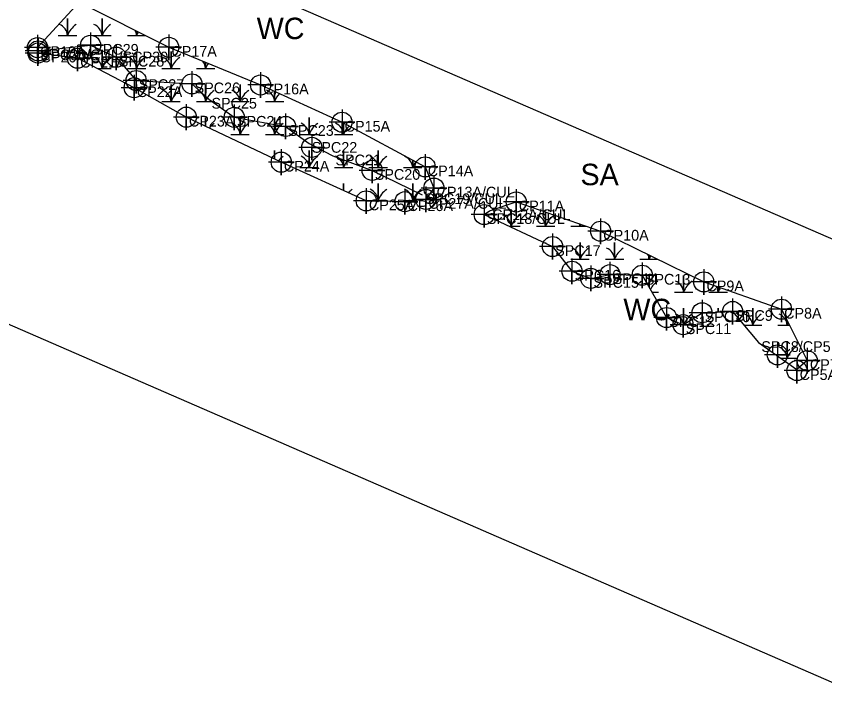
# Model space of a CAD drawing. Extents: x 1253697 to 1278588, y 912189 to 981699.
# Drawn here: x 1258689 to 1259443, y 914396 to 915036 of the extents above; entities that cross this region are included whole.
import ezdxf

# ---------------------------------------------------------------- set-up
doc = ezdxf.new("R2010")
doc.units = 0
for name, color, linetype in [('Default', 7, 'Continuous'), ('Exist Environmental Wetland Boundary', 7, 'Continuous'), ('Exist Environmental Wetland Boundary Cogo Comment', 7, 'Continuous'), ('Exist Environmental Wetland Boundary Cogo Number', 7, 'Continuous'), ('Exist Environmental Wetland Boundary Cogo Point CELL', 7, 'Continuous'), ('Exist Hydro Jurisdictional Stream or Body of Water Mitigable', 7, 'Continuous'), ('Exist Hydro Jurisdictional Stream or Body of Water Mitigable Cogo Comment', 7, 'Continuous'), ('Exist Hydro Jurisdictional Stream or Body of Water Mitigable Cogo Number', 7, 'Continuous'), ('Exist Hydro Jurisdictional Stream or Body of Water Mitigable Cogo Point CELL', 7, 'Continuous'), ('Exist Hydro Swamp or Marsh', 7, 'Continuous')]:
    doc.layers.add(name, color=color, linetype=linetype)

msp = doc.modelspace()

# ---------------------------------------------------------------- linework, layer by layer
at = {"layer": 'Default'}
for points in [[(1259882.27, 914640.07), (1258730.68, 915140.33), (1258752.58, 915140.13), (1259232.78, 915134.84)], [(1259882.27, 914640.07), (1258730.68, 915140.33), (1258752.58, 915140.13), (1259232.78, 915134.84)], [(1259882.27, 914640.07), (1258730.68, 915140.33), (1258752.58, 915140.13), (1259232.78, 915134.84)], [(1259882.27, 914640.07), (1258730.68, 915140.33), (1258752.58, 915140.13), (1259232.78, 915134.84)], [(1258166.63, 914972.26), (1258388.79, 914875.66), (1259491.8, 914396.09)], [(1258166.63, 914972.26), (1258388.79, 914875.66), (1259491.8, 914396.09)], [(1258166.63, 914972.26), (1258388.79, 914875.66), (1259491.8, 914396.09)], [(1258166.63, 914972.26), (1258388.79, 914875.66), (1259491.8, 914396.09)]]:
    msp.add_lwpolyline(points, dxfattribs=at)
at = {"layer": 'Exist Environmental Wetland Boundary'}
msp.add_lwpolyline([(1258708.45, 915006.43), (1258747.36, 915048.9), (1258830.9, 915006.73), (1258916.61, 914971.6), (1258992.57, 914936.81), (1259070.12, 914895.18), (1259078.33, 914875.39), (1259070.72, 914864.84), (1259051.29, 914862.72), (1259015.2, 914863.46), (1258935.87, 914899.57), (1258847.29, 914941.57), (1258798.67, 914969.06), (1258745.83, 914996.58), (1258708.91, 915001.42)], close=True, dxfattribs=at)
msp.add_lwpolyline([(1259125.23, 914850.69), (1259130.26, 914854.3), (1259155.09, 914862.43), (1259233.84, 914835.13), (1259330.1, 914787.85), (1259402.59, 914762.39), (1259426.59, 914714.42), (1259416.94, 914706.11)], dxfattribs=at)
at = {"layer": 'Exist Environmental Wetland Boundary Cogo Point CELL'}
for points in [[(1258708.45, 915018.43), (1258708.45, 914994.43), (1258708.45, 915006.43), (1258720.45, 915006.43), (1258696.45, 915006.43)], [(1258830.9, 915018.73), (1258830.9, 914994.73), (1258830.9, 915006.73), (1258842.9, 915006.73), (1258818.9, 915006.73)], [(1258708.91, 915013.42), (1258708.91, 914989.42), (1258708.91, 915001.42), (1258720.91, 915001.42), (1258696.91, 915001.42)], [(1258745.83, 915008.58), (1258745.83, 914984.58), (1258745.83, 914996.58), (1258757.83, 914996.58), (1258733.83, 914996.58)], [(1258798.67, 914981.06), (1258798.67, 914957.06), (1258798.67, 914969.06), (1258810.67, 914969.06), (1258786.67, 914969.06)], [(1258916.61, 914983.6), (1258916.61, 914959.6), (1258916.61, 914971.6), (1258928.61, 914971.6), (1258904.61, 914971.6)], [(1258847.29, 914953.57), (1258847.29, 914929.57), (1258847.29, 914941.57), (1258859.29, 914941.57), (1258835.29, 914941.57)], [(1258992.57, 914948.81), (1258992.57, 914924.81), (1258992.57, 914936.81), (1259004.57, 914936.81), (1258980.57, 914936.81)], [(1258935.87, 914911.57), (1258935.87, 914887.57), (1258935.87, 914899.57), (1258947.87, 914899.57), (1258923.87, 914899.57)], [(1259070.12, 914907.18), (1259070.12, 914883.18), (1259070.12, 914895.18), (1259082.12, 914895.18), (1259058.12, 914895.18)], [(1259078.33, 914887.39), (1259078.33, 914863.39), (1259078.33, 914875.39), (1259090.33, 914875.39), (1259066.33, 914875.39)], [(1259015.2, 914875.46), (1259015.2, 914851.46), (1259015.2, 914863.46), (1259027.2, 914863.46), (1259003.2, 914863.46)], [(1259051.29, 914874.72), (1259051.29, 914850.72), (1259051.29, 914862.72), (1259063.29, 914862.72), (1259039.29, 914862.72)], [(1259155.09, 914874.43), (1259155.09, 914850.43), (1259155.09, 914862.43), (1259167.09, 914862.43), (1259143.09, 914862.43)], [(1259233.84, 914847.13), (1259233.84, 914823.13), (1259233.84, 914835.13), (1259245.84, 914835.13), (1259221.84, 914835.13)], [(1259330.1, 914799.85), (1259330.1, 914775.85), (1259330.1, 914787.85), (1259342.1, 914787.85), (1259318.1, 914787.85)], [(1259402.59, 914774.39), (1259402.59, 914750.39), (1259402.59, 914762.39), (1259414.59, 914762.39), (1259390.59, 914762.39)], [(1259426.59, 914726.42), (1259426.59, 914702.42), (1259426.59, 914714.42), (1259438.59, 914714.42), (1259414.59, 914714.42)]]:
    msp.add_lwpolyline(points, dxfattribs=at)
for centre in [(1258708.45, 915006.43), (1258708.91, 915001.42), (1258830.9, 915006.73), (1258745.83, 914996.58), (1258916.61, 914971.6), (1258798.67, 914969.06), (1258847.29, 914941.57), (1258992.57, 914936.81), (1258935.87, 914899.57), (1259070.12, 914895.18), (1259078.33, 914875.39), (1259015.2, 914863.46), (1259051.29, 914862.72), (1259155.09, 914862.43), (1259233.84, 914835.13), (1259330.1, 914787.85), (1259402.59, 914762.39), (1259426.59, 914714.42)]:
    msp.add_circle(centre, 9.38, dxfattribs=at)
at = {"layer": 'Exist Hydro Jurisdictional Stream or Body of Water Mitigable'}
for points in [[(1258709.03, 915003.39), (1258757.97, 915008.6), (1258781.85, 914997.54), (1258800.45, 914975.7), (1258852.55, 914972.63), (1258868.3, 914958.31), (1258892.04, 914941.44), (1258939.98, 914932.88), (1258961.9, 914917.12), (1258983.97, 914905.4), (1259020.67, 914891.92), (1259067.36, 914869.24)], [(1259125.23, 914850.69), (1259188.95, 914820.88), (1259207.15, 914797.82), (1259224.72, 914791.14), (1259242.58, 914794.62), (1259272.66, 914794.09), (1259295.4, 914754.57), (1259310.83, 914747.94), (1259328.51, 914759.1), (1259357.04, 914760.27), (1259381.31, 914731.27), (1259416.94, 914706.11)]]:
    msp.add_lwpolyline(points, dxfattribs=at)
at = {"layer": 'Exist Hydro Jurisdictional Stream or Body of Water Mitigable Cogo Point CELL'}
for points in [[(1258757.97, 915020.6), (1258757.97, 914996.6), (1258757.97, 915008.6), (1258769.97, 915008.6), (1258745.97, 915008.6)], [(1258709.03, 915015.39), (1258709.03, 914991.39), (1258709.03, 915003.39), (1258721.03, 915003.39), (1258697.03, 915003.39)], [(1258781.85, 915009.54), (1258781.85, 914985.54), (1258781.85, 914997.54), (1258793.85, 914997.54), (1258769.85, 914997.54)], [(1258800.45, 914987.7), (1258800.45, 914963.7), (1258800.45, 914975.7), (1258812.45, 914975.7), (1258788.45, 914975.7)], [(1258852.55, 914984.63), (1258852.55, 914960.63), (1258852.55, 914972.63), (1258864.55, 914972.63), (1258840.55, 914972.63)], [(1258892.04, 914953.44), (1258892.04, 914929.44), (1258892.04, 914941.44), (1258904.04, 914941.44), (1258880.04, 914941.44)], [(1258939.98, 914944.88), (1258939.98, 914920.88), (1258939.98, 914932.88), (1258951.98, 914932.88), (1258927.98, 914932.88)], [(1258964.4, 914925.37), (1258964.4, 914901.37), (1258964.4, 914913.37), (1258976.4, 914913.37), (1258952.4, 914913.37)], [(1259020.67, 914903.92), (1259020.67, 914879.92), (1259020.67, 914891.92), (1259032.67, 914891.92), (1259008.67, 914891.92)], [(1259070.72, 914876.84), (1259070.72, 914852.84), (1259070.72, 914864.84), (1259082.72, 914864.84), (1259058.72, 914864.84)], [(1259125.23, 914862.69), (1259125.23, 914838.69), (1259125.23, 914850.69), (1259137.23, 914850.69), (1259113.23, 914850.69)], [(1259188.95, 914832.88), (1259188.95, 914808.88), (1259188.95, 914820.88), (1259200.95, 914820.88), (1259176.95, 914820.88)], [(1259207.15, 914809.82), (1259207.15, 914785.82), (1259207.15, 914797.82), (1259219.15, 914797.82), (1259195.15, 914797.82)], [(1259242.58, 914806.62), (1259242.58, 914782.62), (1259242.58, 914794.62), (1259254.58, 914794.62), (1259230.58, 914794.62)], [(1259272.66, 914806.09), (1259272.66, 914782.09), (1259272.66, 914794.09), (1259284.66, 914794.09), (1259260.66, 914794.09)], [(1259224.72, 914803.14), (1259224.72, 914779.14), (1259224.72, 914791.14), (1259236.72, 914791.14), (1259212.72, 914791.14)], [(1259328.51, 914771.1), (1259328.51, 914747.1), (1259328.51, 914759.1), (1259340.51, 914759.1), (1259316.51, 914759.1)], [(1259357.04, 914772.27), (1259357.04, 914748.27), (1259357.04, 914760.27), (1259369.04, 914760.27), (1259345.04, 914760.27)], [(1259295.4, 914766.57), (1259295.4, 914742.57), (1259295.4, 914754.57), (1259307.4, 914754.57), (1259283.4, 914754.57)], [(1259310.83, 914759.94), (1259310.83, 914735.94), (1259310.83, 914747.94), (1259322.83, 914747.94), (1259298.83, 914747.94)], [(1259398.78, 914731.74), (1259398.78, 914707.74), (1259398.78, 914719.74), (1259410.78, 914719.74), (1259386.78, 914719.74)], [(1259417.08, 914717.12), (1259417.08, 914693.12), (1259417.08, 914705.12), (1259429.08, 914705.12), (1259405.08, 914705.12)]]:
    msp.add_lwpolyline(points, dxfattribs=at)
for centre in [(1258757.97, 915008.6), (1258709.03, 915003.39), (1258781.85, 914997.54), (1258800.45, 914975.7), (1258852.55, 914972.63), (1258892.04, 914941.44), (1258939.98, 914932.88), (1258964.4, 914913.37), (1259020.67, 914891.92), (1259070.72, 914864.84), (1259125.23, 914850.69), (1259188.95, 914820.88), (1259207.15, 914797.82), (1259224.72, 914791.14), (1259242.58, 914794.62), (1259272.66, 914794.09), (1259328.51, 914759.1), (1259357.04, 914760.27), (1259295.4, 914754.57), (1259310.83, 914747.94), (1259398.78, 914719.74), (1259417.08, 914705.12)]:
    msp.add_circle(centre, 9.38, dxfattribs=at)
at = {"layer": 'Exist Hydro Swamp or Marsh'}
msp.add_line((1259281.8, 914778.21), (1259287.73, 914778.21), dxfattribs=at)
for points in [[(1258727.88, 915017.68), (1258736.48, 915017.68), (1258736.48, 915033.46), (1258736.48, 915017.68), (1258745.08, 915017.68)], [(1258760.08, 915017.68), (1258768.68, 915017.68), (1258768.68, 915033.46), (1258768.68, 915017.68), (1258777.29, 915017.68)], [(1258792.29, 915017.68), (1258800.89, 915017.68), (1258800.89, 915021.88)], [(1258800.89, 915021.88), (1258800.89, 915017.68), (1258809.22, 915017.68)], [(1258736.48, 914997.81), (1258736.48, 915002.68), (1258736.48, 914997.81)], [(1258764.42, 914986.9), (1258768.68, 914986.9), (1258768.68, 915002.68), (1258768.68, 914986.9), (1258777.29, 914986.9)], [(1258792.29, 914986.9), (1258800.89, 914986.9), (1258800.89, 915002.68), (1258800.89, 914986.9), (1258809.49, 914986.9)], [(1258824.49, 914986.9), (1258833.09, 914986.9), (1258833.09, 915002.68), (1258833.09, 914986.9), (1258841.69, 914986.9)], [(1258856.69, 914986.9), (1258865.29, 914986.9), (1258865.29, 914992.64)], [(1258865.29, 914992.64), (1258865.29, 914986.9), (1258873.9, 914986.9)], [(1258800.89, 914967.8), (1258800.89, 914971.9), (1258800.89, 914967.8)], [(1258824.49, 914956.12), (1258833.09, 914956.12), (1258833.09, 914971.9), (1258833.09, 914956.12), (1258841.69, 914956.12)], [(1258856.69, 914956.12), (1258865.29, 914956.12), (1258865.29, 914971.9), (1258865.29, 914956.12), (1258873.9, 914956.12)], [(1258888.9, 914956.12), (1258897.5, 914956.12), (1258897.5, 914971.9), (1258897.5, 914956.12), (1258906.1, 914956.12)], [(1258921.1, 914956.12), (1258929.7, 914956.12), (1258929.7, 914965.6)], [(1258929.7, 914965.6), (1258929.7, 914956.12), (1258938.3, 914956.12)], [(1258865.29, 914933.03), (1258865.29, 914941.12), (1258865.29, 914933.03)], [(1258888.9, 914925.34), (1258897.5, 914925.34), (1258897.5, 914941.12), (1258897.5, 914925.34), (1258906.1, 914925.34)], [(1258921.1, 914925.34), (1258929.7, 914925.34), (1258929.7, 914941.12), (1258929.7, 914925.34), (1258938.3, 914925.34)], [(1258953.3, 914925.34), (1258961.9, 914925.34), (1258961.9, 914941.12), (1258961.9, 914925.34), (1258970.51, 914925.34)], [(1258985.51, 914925.34), (1258994.11, 914925.34), (1258994.11, 914935.98)], [(1258994.11, 914935.98), (1258994.11, 914925.34), (1259002.71, 914925.34)], [(1258929.7, 914902.5), (1258929.7, 914910.34), (1258929.7, 914902.5)], [(1258953.3, 914894.56), (1258961.9, 914894.56), (1258961.9, 914910.34), (1258961.9, 914894.56), (1258970.51, 914894.56)], [(1258985.51, 914894.56), (1258994.11, 914894.56), (1258994.11, 914910.34), (1258994.11, 914894.56), (1259002.71, 914894.56)], [(1259017.71, 914894.56), (1259026.31, 914894.56), (1259026.31, 914910.34), (1259026.31, 914894.56), (1259034.91, 914894.56)], [(1259049.91, 914894.56), (1259058.51, 914894.56), (1259058.51, 914901.41)], [(1259058.51, 914901.41), (1259058.51, 914894.56), (1259067.12, 914894.56)], [(1258994.11, 914873.06), (1258994.11, 914879.56), (1258994.11, 914873.06)], [(1259017.71, 914863.78), (1259026.31, 914863.78), (1259026.31, 914879.56), (1259026.31, 914863.78), (1259034.91, 914863.78)], [(1259049.91, 914863.78), (1259058.51, 914863.78), (1259058.51, 914879.56), (1259058.51, 914863.78), (1259060.98, 914863.78)], [(1259148.58, 914839.77), (1259150.32, 914839.77), (1259150.32, 914855.55), (1259150.32, 914839.77), (1259158.92, 914839.77)], [(1259173.92, 914839.77), (1259182.52, 914839.77), (1259182.52, 914852.92)], [(1259182.52, 914852.92), (1259182.52, 914839.77), (1259191.12, 914839.77)], [(1259206.12, 914839.77), (1259214.72, 914839.77), (1259214.72, 914841.76)], [(1259214.72, 914841.76), (1259214.72, 914839.77), (1259220.46, 914839.77)], [(1259182.52, 914823.89), (1259182.52, 914824.77), (1259182.52, 914823.89)], [(1259206.12, 914808.99), (1259214.72, 914808.99), (1259214.72, 914824.77), (1259214.72, 914808.99), (1259223.32, 914808.99)], [(1259238.32, 914808.99), (1259246.93, 914808.99), (1259246.93, 914824.77), (1259246.93, 914808.99), (1259255.53, 914808.99)], [(1259270.53, 914808.99), (1259279.13, 914808.99), (1259279.13, 914812.88)], [(1259279.13, 914812.88), (1259279.13, 914808.99), (1259287.06, 914808.99)], [(1259279.13, 914782.84), (1259279.13, 914793.99), (1259279.13, 914782.84)], [(1259302.73, 914778.21), (1259311.33, 914778.21), (1259311.33, 914793.99), (1259311.33, 914778.21), (1259319.93, 914778.21)], [(1259334.93, 914778.21), (1259343.54, 914778.21), (1259343.54, 914783.13)], [(1259343.54, 914783.13), (1259343.54, 914778.21), (1259352.14, 914778.21)], [(1259311.33, 914748.26), (1259311.33, 914763.21), (1259311.33, 914748.26)], [(1259343.54, 914759.72), (1259343.54, 914763.21), (1259343.54, 914759.72)], [(1259367.79, 914747.43), (1259375.74, 914747.43), (1259375.74, 914763.21), (1259375.74, 914747.43), (1259384.34, 914747.43)], [(1259399.34, 914747.43), (1259407.94, 914747.43), (1259407.94, 914751.7)], [(1259407.94, 914751.7), (1259407.94, 914747.43), (1259410.08, 914747.43)], [(1259402.02, 914716.65), (1259407.94, 914716.65), (1259407.94, 914732.43), (1259407.94, 914716.65), (1259416.54, 914716.65)]]:
    msp.add_lwpolyline(points, dxfattribs=at)
for centre, radius, start, end in [((1258724.22, 915016.79), 12.3, 4.14034, 67.53497), ((1258754.72, 915011.62), 19.22, 122.12745, 161.62219), ((1258756.42, 915016.79), 12.3, 4.14034, 67.53497), ((1258786.93, 915011.62), 19.22, 122.12745, 161.62219), ((1258788.62, 915016.79), 12.3, 4.14034, 28.21943), ((1258819.13, 915011.62), 19.22, 150.40033, 161.62219), ((1258754.72, 914980.84), 19.22, 122.12745, 123.77341), ((1258756.42, 914986.01), 12.3, 4.14034, 67.53497), ((1258786.93, 914980.84), 19.22, 122.12745, 161.62219), ((1258788.62, 914986.01), 12.3, 4.14034, 67.53497), ((1258819.13, 914980.84), 19.22, 122.12745, 161.62219), ((1258820.83, 914986.01), 12.3, 4.14034, 67.53497), ((1258851.33, 914980.84), 19.22, 122.12745, 161.62219), ((1258853.03, 914986.01), 12.3, 4.14034, 38.97094), ((1258883.54, 914980.84), 19.22, 145.70592, 161.62219), ((1258819.13, 914950.06), 19.22, 122.12745, 130.84955), ((1258820.83, 914955.23), 12.3, 4.14034, 67.53497), ((1258851.33, 914950.06), 19.22, 122.12745, 161.62219), ((1258853.03, 914955.23), 12.3, 4.14034, 67.53497), ((1258883.54, 914950.06), 19.22, 122.12745, 161.62219), ((1258885.23, 914955.23), 12.3, 4.14034, 67.53497), ((1258915.74, 914950.06), 19.22, 122.12745, 161.62219), ((1258917.43, 914955.23), 12.3, 4.14034, 67.53497), ((1258947.94, 914950.06), 19.22, 135.50077, 161.62219), ((1258883.54, 914919.28), 19.22, 122.12745, 140.74578), ((1258885.23, 914924.45), 12.3, 4.14034, 67.53497), ((1258915.74, 914919.28), 19.22, 122.12745, 161.62219), ((1258917.43, 914924.45), 12.3, 4.14034, 67.53497), ((1258947.94, 914919.28), 19.22, 122.12745, 161.62219), ((1258949.64, 914924.45), 12.3, 4.14034, 67.53497), ((1258980.15, 914919.28), 19.22, 122.12745, 161.62219), ((1258981.84, 914924.45), 12.3, 4.14034, 67.53497), ((1259012.35, 914919.28), 19.22, 133.29418, 161.62219), ((1258947.94, 914888.5), 19.22, 122.12745, 140.06204), ((1258949.64, 914893.67), 12.3, 4.14034, 67.53497), ((1258980.15, 914888.5), 19.22, 122.12745, 161.62219), ((1258981.84, 914893.67), 12.3, 4.14034, 67.53497), ((1259012.35, 914888.5), 19.22, 122.12745, 161.62219), ((1259014.04, 914893.67), 12.3, 4.14034, 67.53497), ((1259044.55, 914888.5), 19.22, 122.12745, 161.62219), ((1259046.25, 914893.67), 12.3, 4.14034, 67.53497), ((1259076.76, 914888.5), 19.22, 143.54425, 161.62219), ((1259012.35, 914857.71), 19.22, 122.12745, 136.05486), ((1259014.04, 914862.89), 12.3, 4.14034, 67.53497), ((1259044.55, 914857.71), 19.22, 122.12745, 161.62219), ((1259046.25, 914862.89), 12.3, 4.14034, 67.53497), ((1259076.76, 914857.71), 19.22, 122.12745, 161.62219), ((1259138.05, 914838.88), 12.3, 4.14034, 67.53497), ((1259168.56, 914833.71), 19.22, 122.12745, 161.62219), ((1259170.25, 914838.88), 12.3, 4.14034, 67.53497), ((1259200.76, 914833.71), 19.22, 122.12745, 161.62219), ((1259202.46, 914838.88), 12.3, 4.14034, 14.08631), ((1259232.97, 914833.71), 19.22, 156.01734, 161.62219), ((1259200.76, 914802.93), 19.22, 122.12745, 122.75713), ((1259202.46, 914808.1), 12.3, 4.14034, 67.53497), ((1259232.97, 914802.93), 19.22, 122.12745, 161.62219), ((1259234.66, 914808.1), 12.3, 4.14034, 67.53497), ((1259265.17, 914802.93), 19.22, 122.12745, 161.62219), ((1259266.86, 914808.1), 12.3, 4.14034, 25.90829), ((1259297.37, 914802.93), 19.22, 151.17882, 161.62219), ((1259297.37, 914772.15), 19.22, 122.12745, 152.93873), ((1259299.07, 914777.32), 12.3, 4.14034, 67.53497), ((1259329.57, 914772.15), 19.22, 122.12745, 161.62219), ((1259331.27, 914777.32), 12.3, 4.14034, 31.56599), ((1259361.78, 914772.15), 19.22, 147.66779, 161.62219), ((1259299.07, 914746.54), 12.3, 7.78883, 67.53497), ((1259329.57, 914741.37), 19.22, 122.12745, 158.19598), ((1259363.47, 914746.54), 12.3, 4.14034, 67.53497), ((1259393.98, 914741.37), 19.22, 122.12745, 161.62219), ((1259395.68, 914746.54), 12.3, 4.14034, 67.53497), ((1259426.18, 914741.37), 19.22, 154.03735, 161.62219), ((1259395.68, 914715.76), 12.3, 4.14034, 67.53497), ((1259426.18, 914710.58), 19.22, 122.12745, 161.62219)]:
    msp.add_arc(centre, radius, start, end, dxfattribs=at)

# ---------------------------------------------------------------- texts
at = {"layer": 'Exist Environmental Wetland Boundary Cogo Comment'}
for s, p in [('CP19A', (1258710.95, 914997.68)), ('CP20A/CUL/SCP30', (1258711.41, 914992.67)), ('CP17A', (1258833.4, 914997.98)), ('CP21A', (1258748.33, 914987.83)), ('CP16A', (1258919.11, 914962.85)), ('CP22A', (1258801.17, 914960.31)), ('CP23A', (1258849.79, 914932.82)), ('CP15A', (1258995.07, 914928.06)), ('CP24A', (1258938.37, 914890.82)), ('CP14A', (1259072.62, 914886.43)), ('CP13A/CUL', (1259080.83, 914866.64)), ('CP27A/CUL', (1259073.22, 914856.09)), ('CP25A', (1259017.7, 914854.71)), ('CP26A', (1259053.79, 914853.97)), ('CP11A', (1259157.59, 914853.68)), ('CP12A/CUL', (1259132.76, 914845.55)), ('CP10A', (1259236.34, 914826.38)), ('CP9A', (1259332.6, 914779.1)), ('CP8A', (1259405.09, 914753.64)), ('CP7A/CUL', (1259429.09, 914705.67)), ('CP5A/CP4/CUL', (1259419.58, 914696.37))]:
    msp.add_text(s, height=10, dxfattribs=at).set_placement(p)
at = {"layer": 'Exist Environmental Wetland Boundary Cogo Number'}
for p in [(1258912.98, 915014.36), (1259255.11, 914752.12)]:
    msp.add_text('WC', height=20, dxfattribs=at).set_placement(p)
at = {"layer": 'Exist Hydro Jurisdictional Stream or Body of Water Mitigable Cogo Comment'}
for s, p in [('SPC29', (1258760.47, 914999.85)), ('SPC30/CUL', (1258711.53, 914994.64)), ('SPC28', (1258784.35, 914988.79)), ('SPC27', (1258802.95, 914966.95)), ('SPC26', (1258855.05, 914963.88)), ('SPC25', (1258870.8, 914949.56)), ('SPC24', (1258894.54, 914932.69)), ('SPC23', (1258942.48, 914924.13)), ('SPC22', (1258964.4, 914908.37)), ('SPC21', (1258986.47, 914896.65)), ('SPC20', (1259023.17, 914883.17)), ('SPC19/CUL', (1259069.86, 914860.49)), ('SPC18/CUL', (1259127.73, 914841.94)), ('SPC17', (1259191.45, 914812.13)), ('SPC16', (1259209.65, 914789.07)), ('SPC15', (1259227.22, 914782.39)), ('SPC14', (1259245.08, 914785.88)), ('SPC13', (1259275.16, 914785.34)), ('SPC9', (1259359.54, 914751.52)), ('SPC12', (1259297.9, 914745.82)), ('SPC10', (1259331.01, 914750.35)), ('SPC11', (1259313.33, 914739.19)), ('SPC8/CP5', (1259383.81, 914722.52))]:
    msp.add_text(s, height=10, dxfattribs=at).set_placement(p)
at = {"layer": 'Exist Hydro Jurisdictional Stream or Body of Water Mitigable Cogo Number'}
msp.add_text('SA', height=20, dxfattribs=at).set_placement((1259215.07, 914878.09))

doc.saveas('drawing.dxf')
